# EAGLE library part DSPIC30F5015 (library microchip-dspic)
dsPIC Motion Controller DSP
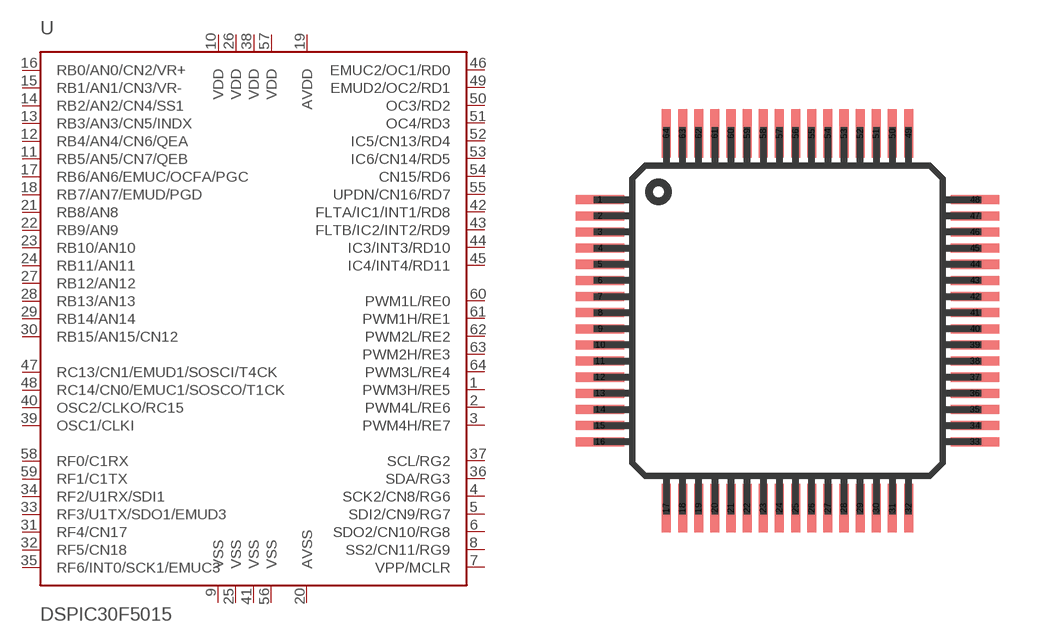
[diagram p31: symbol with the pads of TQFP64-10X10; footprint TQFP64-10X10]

Designator prefix -

## DSPIC30F5015/PF  [TQFP64-10X10]
1  PWM3H/RE5
2  PWM4L/RE6
3  PWM4H/RE7
4  SCK2/CN8/RG6
5  SDI2/CN9/RG7
6  SDO2/CN10/RG8
7  VPP/MCLR  in
8  SS2/CN11/RG9
9  VSS  pwr
10  VDD  pwr
11  RB5/AN5/CN7/QEB
12  RB4/AN4/CN6/QEA
13  RB3/AN3/CN5/INDX
14  RB2/AN2/CN4/SS1
15  RB1/AN1/CN3/VR-
16  RB0/AN0/CN2/VR+
17  RB6/AN6/EMUC/OCFA/PGC
18  RB7/AN7/EMUD/PGD
19  AVDD  pwr
20  AVSS  pwr
21  RB8/AN8
22  RB9/AN9
23  RB10/AN10
24  RB11/AN11
25  VSS  pwr
26  VDD  pwr
27  RB12/AN12
28  RB13/AN13
29  RB14/AN14
30  RB15/AN15/CN12
31  RF4/CN17
32  RF5/CN18
33  RF3/U1TX/SDO1/EMUD3
34  RF2/U1RX/SDI1
35  RF6/INT0/SCK1/EMUC3
36  SDA/RG3
37  SCL/RG2
38  VDD  pwr
39  OSC1/CLKI  in
40  OSC2/CLKO/RC15
41  VSS  pwr
42  FLTA/IC1/INT1/RD8
43  FLTB/IC2/INT2/RD9
44  IC3/INT3/RD10
45  IC4/INT4/RD11
46  EMUC2/OC1/RD0
47  RC13/CN1/EMUD1/SOSCI/T4CK
48  RC14/CN0/EMUC1/SOSCO/T1CK
49  EMUD2/OC2/RD1
50  OC3/RD2
51  OC4/RD3
52  IC5/CN13/RD4
53  IC6/CN14/RD5
54  CN15/RD6
55  UPDN/CN16/RD7
56  VSS  pwr
57  VDD  pwr
58  RF0/C1RX
59  RF1/C1TX
60  PWM1L/RE0
61  PWM1H/RE1
62  PWM2L/RE2
63  PWM2H/RE3
64  PWM3L/RE4

## Footprint TQFP64-10X10 (pad centres in mm)
Thin Quad Flat Pack package type TQ
smd 1.5 x 0.28: 1 -5.8,3.75; 2 -5.8,3.25; 3 -5.8,2.75; 4 -5.8,2.25; 5 -5.8,1.75; 6 -5.8,1.25; 7 -5.8,0.75; 8 -5.8,0.25; 9 -5.8,-0.25; 10 -5.8,-0.75; 11 -5.8,-1.25; 12 -5.8,-1.75; 13 -5.8,-2.25; 14 -5.8,-2.75; 15 -5.8,-3.25; 16 -5.8,-3.75; 33 5.8,-3.75; 34 5.8,-3.25; 35 5.8,-2.75; 36 5.8,-2.25; 37 5.8,-1.75; 38 5.8,-1.25; 39 5.8,-0.75; 40 5.8,-0.25; 41 5.8,0.25; 42 5.8,0.75; 43 5.8,1.25; 44 5.8,1.75; 45 5.8,2.25; 46 5.8,2.75; 47 5.8,3.25; 48 5.8,3.75
smd 0.28 x 1.5: 17 -3.75,-5.8; 18 -3.25,-5.8; 19 -2.75,-5.8; 20 -2.25,-5.8; 21 -1.75,-5.8; 22 -1.25,-5.8; 23 -0.75,-5.8; 24 -0.25,-5.8; 25 0.25,-5.8; 26 0.75,-5.8; 27 1.25,-5.8; 28 1.75,-5.8; 29 2.25,-5.8; 30 2.75,-5.8; 31 3.25,-5.8; 32 3.75,-5.8; 49 3.75,5.8; 50 3.25,5.8; 51 2.75,5.8; 52 2.25,5.8; 53 1.75,5.8; 54 1.25,5.8; 55 0.75,5.8; 56 0.25,5.8; 57 -0.25,5.8; 58 -0.75,5.8; 59 -1.25,5.8; 60 -1.75,5.8; 61 -2.25,5.8; 62 -2.75,5.8; 63 -3.25,5.8; 64 -3.75,5.8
